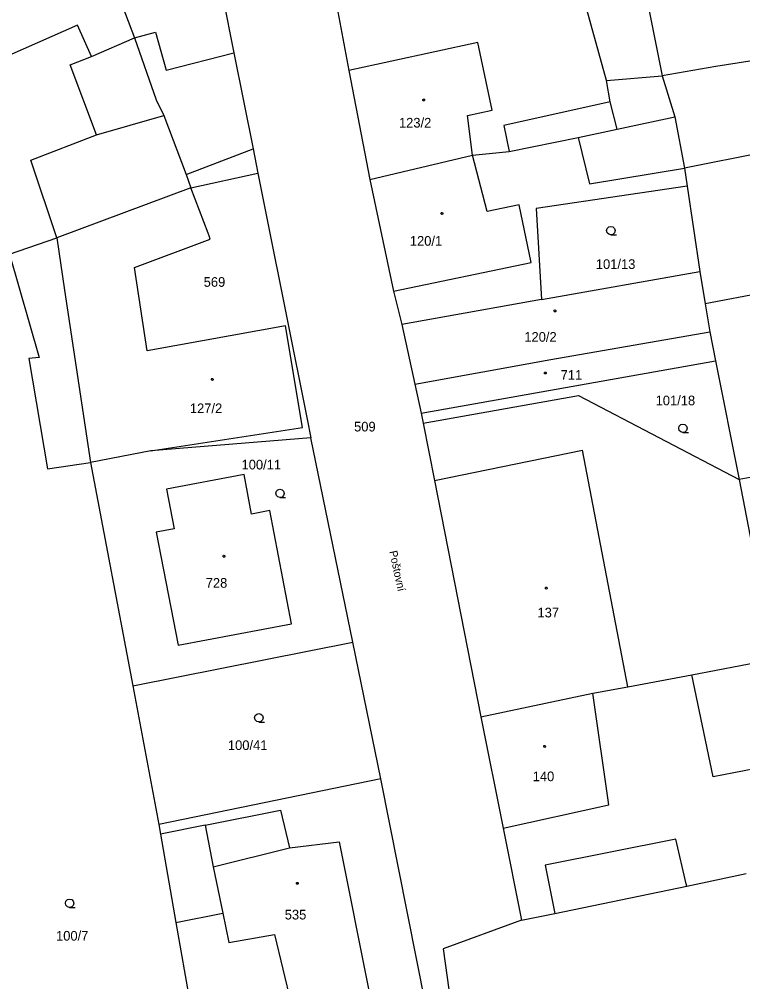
# Model space of a CAD drawing. Extents: x -757994 to -755874, y -1047691 to -1046119.
# Drawn here: x -756956 to -756892.4, y -1047102.2 to -1047017.6 of the extents above; entities that cross this region are included whole.
import ezdxf

# ---------------------------------------------------------------- set-up
doc = ezdxf.new("R2010")
doc.units = 0
doc.layers.add('katastrální mapa', color=7, linetype='Continuous')

msp = doc.modelspace()

# ---------------------------------------------------------------- linework, layer by layer
at = {"layer": 'katastrální mapa'}
for p, q in [((-756940.97, -1047001.2), (-756937.1, -1047020.52)), ((-756951.54, -1047004.15), (-756945.82, -1047019.22)), ((-756901.7, -1047011.21), (-756899.46, -1047022.56)), ((-756904.35, -1047022.97), (-756907.18, -1047012.77)), ((-756928.15, -1047015.99), (-756926.98, -1047022.09)), ((-756950.84, -1047018.11), (-756960.83, -1047022.49)), ((-756949.6, -1047020.86), (-756950.84, -1047018.11)), ((-756949.6, -1047020.86), (-756945.82, -1047019.22)), ((-756945.82, -1047019.22), (-756943.99, -1047018.71)), ((-756945.82, -1047019.22), (-756943.94, -1047024.67)), ((-756943.99, -1047018.71), (-756943.06, -1047022.04)), ((-756915.66, -1047019.62), (-756926.98, -1047022.09)), ((-756914.41, -1047025.57), (-756915.66, -1047019.62)), ((-756881.94, -1047019.74), (-756894.75, -1047021.73)), ((-756951.49, -1047021.59), (-756949.6, -1047020.86)), ((-756943.06, -1047022.04), (-756937.1, -1047020.52)), ((-756937.1, -1047020.52), (-756935.41, -1047028.98)), ((-756949.17, -1047027.74), (-756951.49, -1047021.59)), ((-756894.75, -1047021.73), (-756899.46, -1047022.56)), ((-756926.98, -1047022.09), (-756925.15, -1047031.68)), ((-756904.35, -1047022.97), (-756899.46, -1047022.56)), ((-756899.46, -1047022.56), (-756898.33, -1047026.17)), ((-756904.04, -1047024.83), (-756904.35, -1047022.97)), ((-756943.94, -1047024.67), (-756943.24, -1047026.04)), ((-756904.04, -1047024.83), (-756913.38, -1047026.93)), ((-756903.41, -1047027.25), (-756904.04, -1047024.83)), ((-756949.17, -1047027.74), (-756943.24, -1047026.04)), ((-756943.24, -1047026.04), (-756941.3, -1047031.24)), ((-756916.56, -1047026.05), (-756914.41, -1047025.57)), ((-756916.13, -1047029.53), (-756916.56, -1047026.05)), ((-756903.41, -1047027.25), (-756898.33, -1047026.17)), ((-756898.33, -1047026.17), (-756897.49, -1047030.68)), ((-756913.38, -1047026.93), (-756912.9, -1047029.2)), ((-756954.95, -1047029.97), (-756949.17, -1047027.74)), ((-756906.84, -1047027.96), (-756903.41, -1047027.25)), ((-756912.9, -1047029.2), (-756906.84, -1047027.96)), ((-756906.84, -1047027.96), (-756905.85, -1047032.05)), ((-756886.6, -1047028.5), (-756897.49, -1047030.68)), ((-756941.3, -1047031.24), (-756935.41, -1047028.98)), ((-756935.41, -1047028.98), (-756934.98, -1047031.11)), ((-756925.15, -1047031.68), (-756916.13, -1047029.53)), ((-756916.13, -1047029.53), (-756912.9, -1047029.2)), ((-756914.85, -1047034.48), (-756916.13, -1047029.53)), ((-756952.67, -1047036.8), (-756954.95, -1047029.97)), ((-756941.3, -1047031.24), (-756940.89, -1047032.39)), ((-756940.89, -1047032.39), (-756934.98, -1047031.11)), ((-756934.98, -1047031.11), (-756934.25, -1047034.77)), ((-756905.85, -1047032.05), (-756897.49, -1047030.68)), ((-756897.49, -1047030.68), (-756897.25, -1047032.26)), ((-756925.15, -1047031.68), (-756923.06, -1047041.47)), ((-756940.89, -1047032.39), (-756952.67, -1047036.8)), ((-756939.37, -1047036.38), (-756940.89, -1047032.39)), ((-756897.25, -1047032.26), (-756910.54, -1047034.23)), ((-756897.25, -1047032.26), (-756896.16, -1047039.76)), ((-756912.03, -1047033.88), (-756914.85, -1047034.48)), ((-756910.96, -1047038.97), (-756912.03, -1047033.88)), ((-756910.54, -1047034.23), (-756910.05, -1047042.23)), ((-756934.25, -1047034.77), (-756930.65, -1047052.74)), ((-756956.83, -1047038.22), (-756952.67, -1047036.8)), ((-756952.67, -1047036.8), (-756951.98, -1047041.4)), ((-756945.84, -1047039.4), (-756939.18, -1047036.9)), ((-756939.28, -1047036.63), (-756939.37, -1047036.38)), ((-756939.18, -1047036.9), (-756939.28, -1047036.63)), ((-756956.83, -1047038.22), (-756954.2, -1047047.31)), ((-756944.71, -1047046.73), (-756945.84, -1047039.4)), ((-756923.06, -1047041.47), (-756910.96, -1047038.97)), ((-756910.05, -1047042.23), (-756896.16, -1047039.76)), ((-756896.16, -1047039.76), (-756895.67, -1047042.61)), ((-756884.27, -1047040.41), (-756895.67, -1047042.61)), ((-756951.98, -1047041.4), (-756949.69, -1047056.55)), ((-756923.06, -1047041.47), (-756922.33, -1047044.41)), ((-756910.05, -1047042.23), (-756922.33, -1047044.41)), ((-756895.67, -1047042.61), (-756895.28, -1047045.05)), ((-756932.55, -1047044.53), (-756944.71, -1047046.73)), ((-756931.06, -1047053.48), (-756932.55, -1047044.53)), ((-756922.33, -1047044.41), (-756921.2, -1047049.66)), ((-756909.25, -1047047.48), (-756895.28, -1047045.05)), ((-756895.28, -1047045.05), (-756894.77, -1047047.6)), ((-756954.2, -1047047.31), (-756955.13, -1047047.41)), ((-756955.13, -1047047.41), (-756953.47, -1047057.12)), ((-756921.2, -1047049.66), (-756909.25, -1047047.48)), ((-756920.65, -1047052.2), (-756894.77, -1047047.6)), ((-756894.77, -1047047.6), (-756892.69, -1047058.03)), ((-756921.2, -1047049.66), (-756920.65, -1047052.2)), ((-756920.46, -1047053.08), (-756906.8, -1047050.65)), ((-756906.8, -1047050.65), (-756892.69, -1047058.03)), ((-756920.65, -1047052.2), (-756920.46, -1047053.08)), ((-756930.65, -1047052.74), (-756930.32, -1047054.38)), ((-756920.46, -1047053.08), (-756919.47, -1047058.12)), ((-756944.41, -1047055.53), (-756931.06, -1047053.48)), ((-756930.32, -1047054.38), (-756944.41, -1047055.53)), ((-756926.64, -1047072.34), (-756930.32, -1047054.38)), ((-756944.41, -1047055.53), (-756949.69, -1047056.55)), ((-756919.47, -1047058.12), (-756906.46, -1047055.46)), ((-756902.47, -1047076.26), (-756906.46, -1047055.46)), ((-756953.47, -1047057.12), (-756949.69, -1047056.55)), ((-756949.69, -1047056.55), (-756945.99, -1047076.2)), ((-756882.6, -1047056.19), (-756892.69, -1047058.03)), ((-756936.19, -1047057.61), (-756943.01, -1047058.89)), ((-756935.56, -1047061.09), (-756936.19, -1047057.61)), ((-756919.47, -1047058.12), (-756915.4, -1047078.92)), ((-756892.69, -1047058.03), (-756889.66, -1047073.85)), ((-756943.01, -1047058.89), (-756942.34, -1047062.38)), ((-756933.93, -1047060.78), (-756935.56, -1047061.09)), ((-756932.04, -1047070.73), (-756933.93, -1047060.78)), ((-756942.34, -1047062.38), (-756943.92, -1047062.68)), ((-756943.92, -1047062.68), (-756941.98, -1047072.62)), ((-756941.98, -1047072.62), (-756932.04, -1047070.73)), ((-756945.99, -1047076.2), (-756926.64, -1047072.34)), ((-756924.17, -1047084.37), (-756926.64, -1047072.34)), ((-756896.86, -1047075.22), (-756889.66, -1047073.85)), ((-756902.47, -1047076.26), (-756896.86, -1047075.22)), ((-756894.98, -1047084.18), (-756896.86, -1047075.22)), ((-756945.99, -1047076.2), (-756943.7, -1047088.39)), ((-756915.4, -1047078.92), (-756905.54, -1047076.83)), ((-756905.54, -1047076.83), (-756902.47, -1047076.26)), ((-756904.14, -1047086.64), (-756905.54, -1047076.83)), ((-756915.4, -1047078.92), (-756913.44, -1047088.69)), ((-756887.9, -1047082.8), (-756894.98, -1047084.18)), ((-756924.17, -1047084.37), (-756943.7, -1047088.39)), ((-756916.19, -1047124.64), (-756924.17, -1047084.37)), ((-756939.61, -1047088.45), (-756933.01, -1047087.12)), ((-756933.01, -1047087.12), (-756932.21, -1047090.43)), ((-756913.44, -1047088.69), (-756904.14, -1047086.64)), ((-756943.7, -1047088.39), (-756943.55, -1047089.24)), ((-756939.61, -1047088.45), (-756943.55, -1047089.24)), ((-756939.61, -1047088.45), (-756938.91, -1047092.11)), ((-756913.44, -1047088.69), (-756911.82, -1047096.8)), ((-756943.55, -1047089.24), (-756942.19, -1047097.01)), ((-756898.26, -1047089.67), (-756909.74, -1047091.94)), ((-756897.34, -1047093.6), (-756898.26, -1047089.67)), ((-756938.91, -1047092.11), (-756932.21, -1047090.43)), ((-756932.21, -1047090.43), (-756927.83, -1047089.9)), ((-756927.83, -1047089.9), (-756925.22, -1047103.13)), ((-756938.91, -1047092.11), (-756938.07, -1047096.17)), ((-756909.74, -1047091.94), (-756908.97, -1047095.76)), ((-756897.3, -1047093.79), (-756892.06, -1047092.7)), ((-756908.88, -1047096.19), (-756897.3, -1047093.79)), ((-756897.3, -1047093.79), (-756897.34, -1047093.6)), ((-756942.19, -1047097.01), (-756938.07, -1047096.17)), ((-756938.07, -1047096.17), (-756937.54, -1047098.75)), ((-756911.82, -1047096.8), (-756908.88, -1047096.19)), ((-756908.97, -1047095.76), (-756908.88, -1047096.19)), ((-756942.19, -1047097.01), (-756937.11, -1047126.01)), ((-756911.82, -1047096.8), (-756918.71, -1047099.31)), ((-756937.54, -1047098.75), (-756933.52, -1047098.04)), ((-756933.52, -1047098.04), (-756931.99, -1047104.48)), ((-756918.71, -1047099.31), (-756915.14, -1047124.48))]:
    msp.add_line(p, q, dxfattribs=at)
for points in [[(-756920.41, -1047024.585), (-756920.36, -1047024.595), (-756920.335, -1047024.64), (-756920.325, -1047024.67), (-756920.335, -1047024.715), (-756920.375, -1047024.75), (-756920.41, -1047024.755), (-756920.455, -1047024.74), (-756920.485, -1047024.71), (-756920.495, -1047024.67), (-756920.485, -1047024.625), (-756920.445, -1047024.59)], [(-756918.81, -1047034.565), (-756918.76, -1047034.575), (-756918.735, -1047034.62), (-756918.725, -1047034.65), (-756918.735, -1047034.695), (-756918.775, -1047034.73), (-756918.81, -1047034.735), (-756918.855, -1047034.72), (-756918.885, -1047034.69), (-756918.895, -1047034.65), (-756918.885, -1047034.605), (-756918.845, -1047034.57)], [(-756908.88, -1047043.135), (-756908.83, -1047043.145), (-756908.805, -1047043.19), (-756908.795, -1047043.22), (-756908.805, -1047043.265), (-756908.845, -1047043.3), (-756908.88, -1047043.305), (-756908.925, -1047043.29), (-756908.955, -1047043.26), (-756908.965, -1047043.22), (-756908.955, -1047043.175), (-756908.915, -1047043.14)], [(-756909.73, -1047048.595), (-756909.68, -1047048.605), (-756909.655, -1047048.65), (-756909.645, -1047048.68), (-756909.655, -1047048.725), (-756909.695, -1047048.76), (-756909.73, -1047048.765), (-756909.775, -1047048.75), (-756909.805, -1047048.72), (-756909.815, -1047048.68), (-756909.805, -1047048.635), (-756909.765, -1047048.6)], [(-756938.99, -1047049.155), (-756938.94, -1047049.165), (-756938.915, -1047049.21), (-756938.905, -1047049.24), (-756938.915, -1047049.285), (-756938.955, -1047049.32), (-756938.99, -1047049.325), (-756939.035, -1047049.31), (-756939.065, -1047049.28), (-756939.075, -1047049.24), (-756939.065, -1047049.195), (-756939.025, -1047049.16)], [(-756937.97, -1047064.705), (-756937.92, -1047064.715), (-756937.895, -1047064.76), (-756937.885, -1047064.79), (-756937.895, -1047064.835), (-756937.935, -1047064.87), (-756937.97, -1047064.875), (-756938.015, -1047064.86), (-756938.045, -1047064.83), (-756938.055, -1047064.79), (-756938.045, -1047064.745), (-756938.005, -1047064.71)], [(-756909.64, -1047067.505), (-756909.59, -1047067.515), (-756909.565, -1047067.56), (-756909.555, -1047067.59), (-756909.565, -1047067.635), (-756909.605, -1047067.67), (-756909.64, -1047067.675), (-756909.685, -1047067.66), (-756909.715, -1047067.63), (-756909.725, -1047067.59), (-756909.715, -1047067.545), (-756909.675, -1047067.51)], [(-756909.78, -1047081.425), (-756909.73, -1047081.435), (-756909.705, -1047081.48), (-756909.695, -1047081.51), (-756909.705, -1047081.555), (-756909.745, -1047081.59), (-756909.78, -1047081.595), (-756909.825, -1047081.58), (-756909.855, -1047081.55), (-756909.865, -1047081.51), (-756909.855, -1047081.465), (-756909.815, -1047081.43)], [(-756931.52, -1047093.465), (-756931.47, -1047093.475), (-756931.445, -1047093.52), (-756931.435, -1047093.55), (-756931.445, -1047093.595), (-756931.485, -1047093.63), (-756931.52, -1047093.635), (-756931.565, -1047093.62), (-756931.595, -1047093.59), (-756931.605, -1047093.55), (-756931.595, -1047093.505), (-756931.555, -1047093.47)]]:
    msp.add_lwpolyline(points, close=True, dxfattribs=at)
for points in [[(-756903.96, -1047036.53), (-756904.15, -1047036.48), (-756904.285, -1047036.345), (-756904.335, -1047036.16), (-756904.285, -1047035.975), (-756904.15, -1047035.84), (-756903.965, -1047035.79), (-756903.78, -1047035.84), (-756903.645, -1047035.975), (-756903.595, -1047036.165), (-756903.645, -1047036.355), (-756903.78, -1047036.49), (-756903.97, -1047036.54), (-756903.47, -1047036.54)], [(-756897.63, -1047053.91), (-756897.82, -1047053.86), (-756897.955, -1047053.725), (-756898.005, -1047053.54), (-756897.955, -1047053.355), (-756897.82, -1047053.22), (-756897.635, -1047053.17), (-756897.45, -1047053.22), (-756897.315, -1047053.355), (-756897.265, -1047053.545), (-756897.315, -1047053.735), (-756897.45, -1047053.87), (-756897.64, -1047053.92), (-756897.14, -1047053.92)], [(-756933.04, -1047059.63), (-756933.23, -1047059.58), (-756933.365, -1047059.445), (-756933.415, -1047059.26), (-756933.365, -1047059.075), (-756933.23, -1047058.94), (-756933.045, -1047058.89), (-756932.86, -1047058.94), (-756932.725, -1047059.075), (-756932.675, -1047059.265), (-756932.725, -1047059.455), (-756932.86, -1047059.59), (-756933.05, -1047059.64), (-756932.55, -1047059.64)], [(-756934.9, -1047079.36), (-756935.09, -1047079.31), (-756935.225, -1047079.175), (-756935.275, -1047078.99), (-756935.225, -1047078.805), (-756935.09, -1047078.67), (-756934.905, -1047078.62), (-756934.72, -1047078.67), (-756934.585, -1047078.805), (-756934.535, -1047078.995), (-756934.585, -1047079.185), (-756934.72, -1047079.32), (-756934.91, -1047079.37), (-756934.41, -1047079.37)], [(-756951.53, -1047095.67), (-756951.72, -1047095.62), (-756951.855, -1047095.485), (-756951.905, -1047095.3), (-756951.855, -1047095.115), (-756951.72, -1047094.98), (-756951.535, -1047094.93), (-756951.35, -1047094.98), (-756951.215, -1047095.115), (-756951.165, -1047095.305), (-756951.215, -1047095.495), (-756951.35, -1047095.63), (-756951.54, -1047095.68), (-756951.04, -1047095.68)]]:
    msp.add_lwpolyline(points, dxfattribs=at)

# ---------------------------------------------------------------- texts
for s, p in [('123/2', (-756922.59, -1047027.1)), ('120/1', (-756921.634, -1047037.49)), ('101/13', (-756905.286, -1047039.53)), ('569', (-756939.751, -1047041.1)), ('120/2', (-756911.574, -1047045.93)), ('711', (-756908.381, -1047049.28)), ('101/18', (-756900.033, -1047051.52)), ('127/2', (-756940.966, -1047052.21)), ('509', (-756926.534, -1047053.82)), ('100/11', (-756936.424, -1047057.16)), ('728', (-756939.571, -1047067.56)), ('137', (-756910.416, -1047070.17)), ('100/41', (-756937.624, -1047081.83)), ('140', (-756910.836, -1047084.57)), ('535', (-756932.627, -1047096.73)), ('100/7', (-756952.729, -1047098.59))]:
    msp.add_text(s, height=0.85, dxfattribs=at).set_placement(p)
msp.add_text('Poštovní', height=0.7, rotation=282.06712, dxfattribs=at).set_placement((-756923.441, -1047064.37))

doc.saveas('drawing.dxf')
